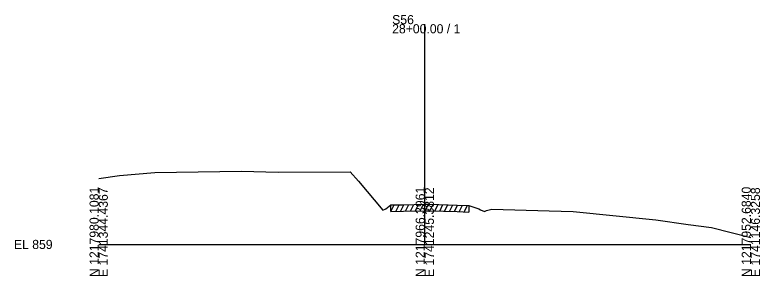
# Model space of a CAD drawing. Extents: x -26 to 1203, y -10 to 19541.
# Drawn here: x -25.7 to 202.8, y 2990.3 to 3070.3 of the extents above; entities that cross this region are included whole.
import ezdxf

# ---------------------------------------------------------------- set-up
doc = ezdxf.new("R2010")
doc.units = 0
for name, color, linetype in [('RD_GPK_XS_Cell', 7, 'Continuous'), ('RD_XS_ExGround', 7, 'Continuous'), ('RD_XS_ExPaveRet', 7, 'Continuous'), ('RD_XS_TX_Elev_EX', 7, 'Continuous')]:
    doc.layers.add(name, color=color, linetype=linetype)

msp = doc.modelspace()

# ---------------------------------------------------------------- linework, layer by layer
at = {"layer": 'RD_GPK_XS_Cell'}
for p, q in [((100, 3000), (100, 3067.48)), ((0, 3000), (100, 3000)), ((100, 3000), (200, 3000))]:
    msp.add_line(p, q, dxfattribs=at)
at = {"layer": 'RD_XS_ExGround'}
msp.add_lwpolyline([(0, 3020.21), (6.42, 3021.09), (17.26, 3022.06), (43.81, 3022.49), (55.06, 3022.19), (77.17, 3022.25), (79.73, 3019.43), (87.1, 3010.53), (88.08, 3010.96), (89.6, 3012.1), (93.47, 3012.16), (100, 3012.3), (101.52, 3012.34), (109.98, 3012.07), (113.56, 3011.92), (114.48, 3011.62), (116.61, 3010.88), (117.1, 3010.63), (118.31, 3010.12), (118.98, 3010.37), (120.61, 3010.76), (138.18, 3010.31), (145.47, 3010.08), (170.91, 3007.49), (180.77, 3006.14), (187.89, 3005.16), (200, 3002.12)], dxfattribs=at)
at = {"layer": 'RD_XS_ExPaveRet'}
for p, q in [((89.6, 3010.1), (90.61, 3012.11)), ((89.6, 3010.1), (89.6, 3012.1)), ((91.1, 3010.12), (92.11, 3012.14)), ((92.6, 3010.14), (93.61, 3012.16)), ((94.1, 3010.17), (95.11, 3012.19)), ((95.6, 3010.2), (96.61, 3012.23)), ((97.1, 3010.24), (98.11, 3012.26)), ((98.6, 3010.27), (99.61, 3012.29)), ((100.1, 3010.31), (101.11, 3012.33)), ((101.6, 3010.33), (102.59, 3012.3)), ((103.1, 3010.29), (104.09, 3012.26)), ((104.6, 3010.24), (105.59, 3012.21)), ((106.1, 3010.19), (107.09, 3012.16)), ((107.6, 3010.14), (108.59, 3012.11)), ((109.1, 3010.09), (110.09, 3012.06)), ((89.6, 3010.1), (93.47, 3010.16)), ((93.47, 3010.16), (100, 3010.3)), ((100, 3010.3), (101.52, 3010.34)), ((101.52, 3010.34), (109.98, 3010.07)), ((109.98, 3010.07), (113.56, 3009.92)), ((110.6, 3010.04), (111.58, 3012)), ((112.1, 3009.98), (113.08, 3011.94)), ((113.56, 3011.92), (113.56, 3009.92))]:
    msp.add_line(p, q, dxfattribs=at)

# ---------------------------------------------------------------- texts
at = {"layer": 'RD_GPK_XS_Cell'}
for s, p in [('S56', (90, 3067.48)), ('28+00.00 / 1', (90, 3064.68)), ('EL 859', (-26, 2998.6))]:
    msp.add_text(s, height=2.8, dxfattribs=at).set_placement(p)
for s, p in [('N 1217980.1081', (0, 2990)), ('E 1741344.4367', (2.8, 2990)), ('N 1217966.3961', (100, 2990)), ('E 1741245.3812', (102.8, 2990)), ('N 1217952.6840', (200, 2990)), ('E 1741146.3258', (202.8, 2990))]:
    msp.add_text(s, height=2.8, rotation=90, dxfattribs=at).set_placement(p)
at = {"layer": 'RD_XS_TX_Elev_EX'}
msp.add_text('865.15', height=0.1, rotation=90, dxfattribs=at).set_placement((100.1, 3012.3))

doc.saveas('drawing.dxf')
